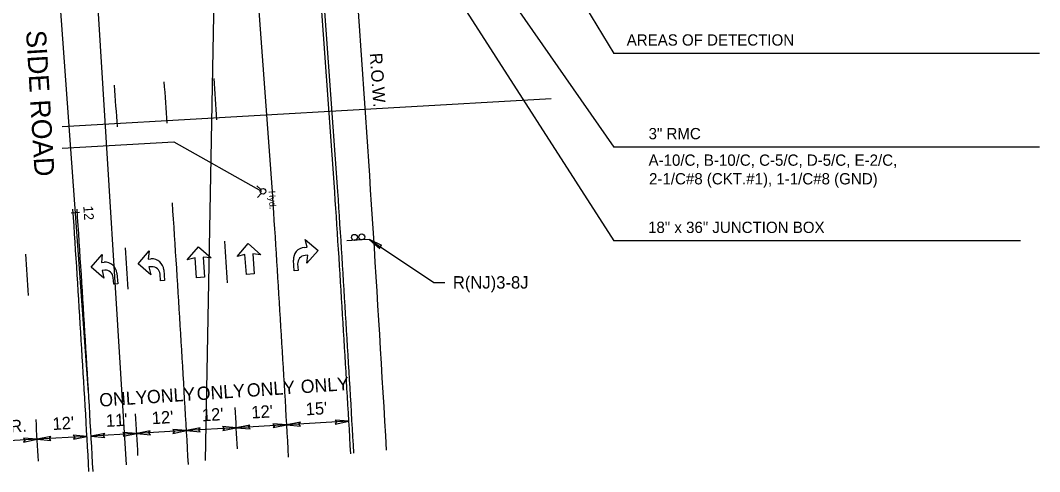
# Model space of a CAD drawing. Extents: x 488740 to 507913, y 466518 to 497949.
# Drawn here: x 503498.8 to 503744.5, y 495808.3 to 495917 of the extents above; entities that cross this region are included whole.
import ezdxf

# ---------------------------------------------------------------- set-up
doc = ezdxf.new("R2010")
doc.units = 0
for name, color, linetype in [('1', 7, 'Continuous'), ('23', 7, 'Continuous'), ('36', 7, 'Continuous'), ('38', 7, 'Continuous'), ('41', 7, 'Continuous'), ('9', 7, 'Continuous')]:
    doc.layers.add(name, color=color, linetype=linetype)

msp = doc.modelspace()

# ---------------------------------------------------------------- linework, layer by layer
at = {"layer": '1'}
for p, q in [((503515.23, 495827.41), (503497.67, 496070.42)), ((503559.65, 495874.65), (503550.66, 495999.1)), ((503574.61, 495875.73), (503568.16, 495964.96)), ((503575.36, 495875.79), (503568.91, 495965.02)), ((503513.09, 495870.69), (503511.1, 495870.54))]:
    msp.add_line(p, q, dxfattribs=at)
for centre, radius, start, end in [((496341.87, 495401.78), 7256.91, 3.252403, 4.133489), ((496341.87, 495401.78), 7233.26, 3.249458, 3.748381), ((496341.87, 495401.78), 7248.26, 3.249458, 3.748381), ((496342.61, 495401.93), 7248.26, 3.249458, 3.748381)]:
    msp.add_arc(centre, radius, start, end, dxfattribs=at)
at = {"layer": '23'}
for p, q in [((503524.39, 495809.94), (503494.31, 496296.44)), ((503546.14, 495959.54), (503543.42, 495811.02)), ((503508.94, 495891.45), (503626.81, 495898.16)), ((503508.94, 495886.21), (503535.84, 495887.75)), ((503535.84, 495887.75), (503556.97, 495875.85)), ((503556.81, 495876.28), (503555.81, 495877.18)), ((503556.87, 495875.33), (503555.96, 495874.32))]:
    msp.add_line(p, q, dxfattribs=at)
msp.add_circle((503557.32, 495875.83), 0.675, dxfattribs=at)
at = {"layer": '36'}
for p, q in [((503567.95, 495862.35), (503567.49, 495864.25)), ((503567.49, 495864.25), (503570.58, 495861.58)), ((503527.2, 495858.37), (503529.86, 495861.46)), ((503529.86, 495861.46), (503529.68, 495859.51)), ((503539.08, 495859.36), (503541.75, 495862.44)), ((503541.75, 495862.44), (503544.83, 495859.77)), ((503551.07, 495860.15), (503553.74, 495863.23)), ((503553.74, 495863.23), (503556.83, 495860.56)), ((503567.31, 495862.31), (503567.95, 495862.35)), ((503570.58, 495861.58), (503567.91, 495858.49)), ((503515.9, 495857.55), (503518.57, 495860.64)), ((503518.57, 495860.64), (503518.39, 495858.7)), ((503529.68, 495859.51), (503530.32, 495859.56)), ((503540.97, 495859.82), (503539.08, 495859.36)), ((503541.32, 495855.02), (503540.97, 495859.82)), ((503544.83, 495859.77), (503542.89, 495859.95)), ((503542.89, 495859.95), (503543.24, 495855.16)), ((503552.97, 495860.6), (503551.07, 495860.15)), ((503553.32, 495855.81), (503552.97, 495860.6)), ((503556.83, 495860.56), (503554.89, 495860.74)), ((503554.89, 495860.74), (503555.23, 495855.95)), ((503564.83, 495856.66), (503564.64, 495859.22)), ((503568.09, 495860.43), (503567.45, 495860.39)), ((503567.91, 495858.49), (503568.09, 495860.43)), ((503518.99, 495854.89), (503515.9, 495857.55)), ((503518.39, 495858.7), (503519.03, 495858.74)), ((503519.17, 495856.83), (503518.53, 495856.78)), ((503518.53, 495856.78), (503518.99, 495854.89)), ((503530.28, 495855.7), (503527.2, 495858.37)), ((503530.46, 495857.64), (503529.82, 495857.6)), ((503529.82, 495857.6), (503530.28, 495855.7)), ((503533.41, 495856.89), (503533.59, 495854.33)), ((503565.78, 495856.73), (503564.83, 495856.66)), ((503565.67, 495858.33), (503565.78, 495856.73)), ((503521.34, 495853.45), (503521.22, 495855.05)), ((503522.11, 495856.08), (503522.3, 495853.52)), ((503532.63, 495854.26), (503532.52, 495855.86)), ((503533.59, 495854.33), (503532.63, 495854.26)), ((503543.24, 495855.16), (503541.32, 495855.02)), ((503555.23, 495855.95), (503553.32, 495855.81)), ((503522.3, 495853.52), (503521.34, 495853.45))]:
    msp.add_line(p, q, dxfattribs=at)
for centre, radius, start, end in [((496341.87, 495401.78), 7197.03, 3.900558, 3.980294), ((496341.87, 495401.78), 7209.05, 3.900689, 3.980294), ((496341.87, 495401.78), 7221.07, 3.900822, 3.980294), ((496341.87, 495401.78), 7185.02, 3.243828, 3.748344), ((496341.87, 495401.78), 7186.02, 3.243828, 3.748344), ((496341.87, 495401.78), 7209.05, 3.246589, 3.748344), ((496341.87, 495401.78), 7197.03, 3.588553, 3.668292), ((496341.87, 495401.78), 7221.07, 3.588819, 3.668292), ((503567.52, 495859.43), 2.88, 94.1344, 184.1344), ((496341.87, 495401.78), 7173, 3.588553, 3.668292), ((503530.53, 495856.68), 2.88, 4.1344, 94.1344), ((503567.59, 495858.47), 1.92, 94.1344, 184.1344), ((503519.24, 495855.87), 2.88, 4.1344, 94.1344), ((503519.31, 495854.91), 1.92, 4.1344, 94.1344), ((503530.6, 495855.72), 1.92, 4.1344, 94.1344), ((496341.87, 495401.78), 7197.03, 3.2696, 3.349339), ((496341.87, 495401.78), 7221.07, 3.270925, 3.3504), ((496341.87, 495401.78), 7173, 3.2696, 3.349339)]:
    msp.add_arc(centre, radius, start, end, dxfattribs=at)
at = {"layer": '38'}
for p, q in [((503563.05, 495819.6), (503550.88, 495818.89)), ((503578.02, 495820.46), (503563.05, 495819.6)), ((503526.89, 495817.5), (503515.89, 495816.87)), ((503538.89, 495818.2), (503526.89, 495817.5)), ((503550.88, 495818.89), (503538.89, 495818.2)), ((503502.89, 495816.12), (503489, 495815.31)), ((503514.89, 495816.81), (503502.89, 495816.12))]:
    msp.add_line(p, q, dxfattribs=at)
for points in [[(503563.05, 495819.6), (503559.72, 495819.88), (503560.1, 495819.43), (503559.77, 495818.93)], [(503563.05, 495819.6), (503566.38, 495819.32), (503565.99, 495819.77), (503566.32, 495820.26)], [(503578.02, 495820.46), (503574.69, 495820.74), (503575.07, 495820.29), (503574.75, 495819.8)], [(503515.89, 495816.87), (503519.22, 495816.59), (503518.83, 495817.04), (503519.16, 495817.53)], [(503526.89, 495817.5), (503523.56, 495817.78), (503523.94, 495817.33), (503523.61, 495816.84)], [(503526.89, 495817.5), (503530.22, 495817.22), (503529.83, 495817.67), (503530.16, 495818.17)], [(503538.89, 495818.2), (503535.56, 495818.48), (503535.94, 495818.03), (503535.61, 495817.54)], [(503538.89, 495818.2), (503542.21, 495817.92), (503541.83, 495818.37), (503542.16, 495818.86)], [(503550.88, 495818.89), (503547.56, 495819.17), (503547.94, 495818.72), (503547.61, 495818.23)], [(503550.88, 495818.89), (503554.21, 495818.61), (503553.83, 495819.06), (503554.16, 495819.56)], [(503502.89, 495816.12), (503499.56, 495816.4), (503499.94, 495815.94), (503499.61, 495815.45)], [(503502.89, 495816.12), (503506.22, 495815.83), (503505.84, 495816.29), (503506.16, 495816.78)], [(503514.89, 495816.81), (503511.56, 495817.09), (503511.94, 495816.64), (503511.61, 495816.15)]]:
    msp.add_lwpolyline(points, close=True, dxfattribs=at)
at = {"layer": '41'}
for p, q in [((503581.19, 495864.13), (503577.53, 495863.89)), ((503582.95, 495864.26), (503579.3, 495864.02)), ((503582.95, 495864.26), (503598.46, 495853.89)), ((503598.46, 495853.89), (503601.17, 495853.89))]:
    msp.add_line(p, q, dxfattribs=at)
msp.add_lwpolyline([(503582.95, 495864.26), (503585.44, 495862.03), (503585.41, 495862.62), (503585.97, 495862.81)], close=True, dxfattribs=at)
for centre in [(503579.37, 495864.72), (503581.14, 495864.85)]:
    msp.add_circle(centre, 0.721, dxfattribs=at)
at = {"layer": '9'}
for p, q in [((503593.88, 495988.3), (503641.84, 495909.01)), ((503576.6, 495980.13), (503641.84, 495886.46)), ((503572.7, 495971.48), (503641.84, 495863.9)), ((503744.5, 495909.01), (503641.84, 495909.01)), ((503744.5, 495886.46), (503641.84, 495886.46)), ((503739.9, 495863.9), (503641.84, 495863.9))]:
    msp.add_line(p, q, dxfattribs=at)

# ---------------------------------------------------------------- texts
at = {"layer": '1'}
for s, height, rotation, p in [('SIDE ROAD', 4.796, 273.4605, (503500.19, 495914.48)), ('R.O.W.', 2.993, 273.9498, (503583.04, 495909.04)), ('12', 2.344, 274.1335, (503514, 495872.26))]:
    msp.add_text(s, height=height, rotation=rotation, dxfattribs=at).set_placement(p)
at = {"layer": '23'}
msp.add_text('Hyd.', height=1.62, rotation=273.0981, dxfattribs=at).set_placement((503558.66, 495875.9))
at = {"layer": '36'}
for p in [(503541.46, 495825.51), (503553.53, 495826.31), (503566.52, 495827.18), (503517.97, 495823.95), (503529.46, 495824.71)]:
    msp.add_text('ONLY', height=3.193, rotation=3.8987, dxfattribs=at).set_placement(p)
at = {"layer": '38'}
for s, rotation, p in [("15'", 3.3116, (503567.68, 495821.87)), ("11'", 3.3113, (503519.54, 495819.09)), ("12'", 3.3111, (503530.59, 495819.74)), ("12'", 3.3116, (503542.67, 495820.43)), ("12'", 3.3112, (503554.59, 495821.11)), ('VAR.', 3.3115, (503491.13, 495817.43)), ("12'", 3.3116, (503506.66, 495818.34))]:
    msp.add_text(s, height=2.993, rotation=rotation, dxfattribs=at).set_placement(p)
at = {"layer": '41'}
msp.add_text('R(NJ)3-8J', height=2.993, dxfattribs=at).set_placement((503603.08, 495852.4))
at = {"layer": '9'}
for s, p in [('AREAS OF DETECTION           ', (503644.98, 495910.9)), ('3" RMC                                  ', (503650.25, 495888.35)), ('A-10/C, B-10/C, C-5/C, D-5/C, E-2/C,    ', (503650.25, 495881.97)), ('2-1/C#8 (CKT.#1), 1-1/C#8 (GND)         ', (503650.37, 495877.48)), ('18" x 36" JUNCTION BOX       ', (503650.13, 495865.79))]:
    msp.add_text(s, height=2.7163, dxfattribs=at).set_placement(p)

doc.saveas('drawing.dxf')
